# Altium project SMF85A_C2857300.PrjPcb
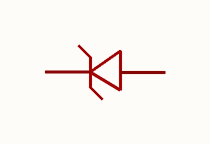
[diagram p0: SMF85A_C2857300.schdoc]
1 sheet, 1 parts. Net scope: global (net labels, ports and power ports of the same name join across sheets).

## Sheet SMF85A_C2857300.schdoc
size 127 x 101 mm

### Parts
D?  smf85a_c2857300  [SOD-123FL_L2.8-W1.8-LS3.6-RD]  (value not drawn)

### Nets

Not connected (* = marked no-connect by the designer): D? 1 2

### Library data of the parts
D? = smf85a_c2857300: 极性:单向;反向截止电压(Vrwm):85V;钳位电压:137V;峰值脉冲电流(Ipp):1.5A;峰值脉冲功率(Ppp):200W@10/1000us;击穿电压(VBR):94.4V;; Manufacturer: JSMSEMI(杰盛微); ManufacturerPart: SMF85A; AddInBom: yes; ModelId: 9a6bf0a398604d2998ad78800a7c8ef9; ModelTransform: 141.732,70.866,0,0,0,0,0,0,0; Polarity: 单向; Reverse Stand-Off Voltage (Vrwm): 85V; Clamping Voltage: 137V; Peak Pulse Current (Ipp): 1.5A; Voltage - Breakdown: 94.4V; Reverse Leakage Current (Ir): 1uA; Number of Channels: 单路; Type: TVS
